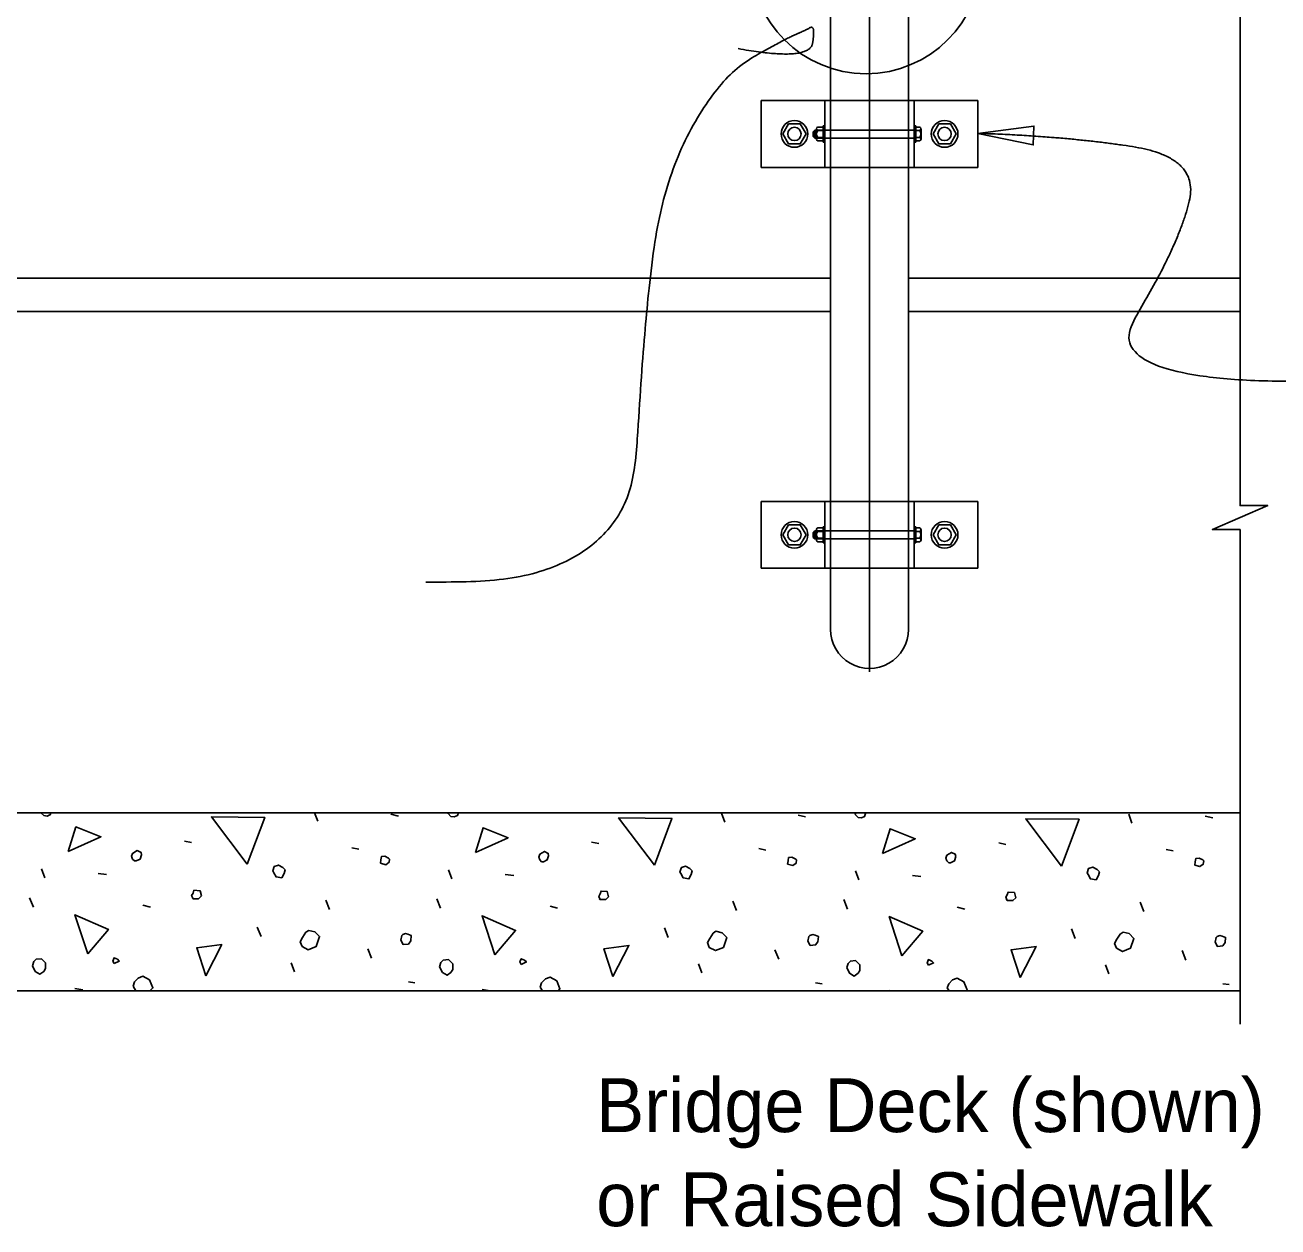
# Model space of a CAD drawing. Extents: x 0 to 41.2, y 0 to 26.
# Drawn here: x 19.046 to 23.735, y 12.586 to 17.084 of the extents above; entities that cross this region are included whole.
import ezdxf

# ---------------------------------------------------------------- set-up
doc = ezdxf.new("R2010")
doc.units = 0
for name, color, linetype in [('CL_Major', 7, 'Continuous'), ('Dimension', 7, 'Continuous'), ('Miscellaneous', 7, 'Continuous'), ('SteelMisc', 7, 'Continuous'), ('SteelMisc_h', 7, 'Continuous'), ('SupstrConc', 7, 'Continuous')]:
    doc.layers.add(name, color=color, linetype=linetype)

msp = doc.modelspace()

# ---------------------------------------------------------------- linework, layer by layer
at = {"layer": 'CL_Major'}
msp.add_line((22.2062, 25.5043), (22.2062, 14.6639), dxfattribs=at)
at = {"layer": 'Dimension'}
for points in [[(23.5932, 20.1983), (23.5932, 19.1806), (23.6966, 19.1806), (23.5932, 19.1356), (23.4899, 19.0906), (23.5932, 19.0906), (23.5932, 16.8862)], [(23.5932, 17.1362), (23.5932, 15.2854), (23.6966, 15.2854), (23.5932, 15.2404), (23.4899, 15.1954), (23.5932, 15.1954), (23.5932, 13.3448)]]:
    msp.add_lwpolyline(points, dxfattribs=at)
msp.add_lwpolyline([(22.6122, 16.6783), (22.819, 16.6352), (22.8216, 16.7057)], close=True, dxfattribs=at)
msp.add_circle((22.1934, 17.3332), 0.4318, dxfattribs=at)
for points in [[(20.5456, 14.9991), (21.3049, 14.9652), (21.3652, 16.0213), (21.4405, 16.5191), (21.6515, 16.8963), (21.8903, 17.0313), (21.9647, 17.0631), (22.0043, 17.0848), (21.982, 16.9466), (21.7151, 16.9952)], [(23.9932, 15.7529), (23.0399, 15.7236), (23.3618, 16.2556), (23.4433, 16.5898), (22.9335, 16.6682), (22.6122, 16.6783)]]:
    msp.add_open_spline(points, degree=2, dxfattribs=at)
at = {"layer": 'Miscellaneous'}
for p, q in [((21.9986, 16.6691), (21.9986, 16.6812)), ((22.0044, 16.6691), (22.0044, 16.6812)), ((21.9986, 15.1691), (21.9986, 15.1812)), ((22.0044, 15.1691), (22.0044, 15.1812)), ((20.141, 14.1043), (20.1292, 14.1361)), ((20.415, 14.1308), (20.4432, 14.1237)), ((21.6648, 14.1008), (21.6524, 14.1344)), ((21.9388, 14.1273), (21.9671, 14.1202)), ((23.1886, 14.0972), (23.1762, 14.1308)), ((23.4626, 14.1237), (23.4909, 14.1167)), ((19.6424, 14.0301), (19.669, 14.0247)), ((21.1663, 14.0265), (21.1928, 14.0212)), ((22.6901, 14.023), (22.7166, 14.0177)), ((20.2682, 14.0053), (20.2947, 14)), ((21.792, 14.0018), (21.8186, 13.9965)), ((23.3159, 13.9982), (23.3424, 13.9929)), ((19.1192, 13.8922), (19.1068, 13.9258)), ((19.3189, 13.9081), (19.3508, 13.9045)), ((20.643, 13.8886), (20.6306, 13.9222)), ((20.8428, 13.9045), (20.8746, 13.901)), ((22.1668, 13.8851), (22.1544, 13.9187)), ((22.3666, 13.901), (22.3984, 13.8975)), ((19.0768, 13.7826), (19.0626, 13.8179)), ((19.4869, 13.7896), (19.5152, 13.7826)), ((20.1851, 13.7737), (20.171, 13.8091)), ((20.6006, 13.779), (20.5864, 13.8144)), ((21.0107, 13.7861), (21.039, 13.779)), ((21.709, 13.7702), (21.6948, 13.8055)), ((22.1244, 13.7755), (22.1102, 13.8108)), ((23.2328, 13.7667), (23.2186, 13.802)), ((22.5345, 13.7826), (22.5628, 13.7755)), ((19.9288, 13.673), (19.9147, 13.7083)), ((21.4526, 13.6694), (21.4385, 13.7048)), ((22.9765, 13.6659), (22.9623, 13.7012)), ((20.3425, 13.5916), (20.3283, 13.627)), ((21.8663, 13.5881), (21.8522, 13.6235)), ((23.3901, 13.5846), (23.376, 13.6199)), ((20.0543, 13.5404), (20.042, 13.574)), ((21.5781, 13.5368), (21.5658, 13.5704)), ((23.102, 13.5333), (23.0896, 13.5669)), ((19.2323, 13.4785), (19.2624, 13.4732)), ((20.4804, 13.5033), (20.5051, 13.4997)), ((20.7561, 13.475), (20.7862, 13.4697)), ((22.0042, 13.4997), (22.0289, 13.4962)), ((22.28, 13.4714), (22.2912, 13.4695)), ((23.528, 13.4962), (23.5527, 13.4927))]:
    msp.add_line(p, q, dxfattribs=at)
for points in [[(19.105, 14.1361), (19.1156, 14.1255)], [(19.1156, 14.1255), (19.128, 14.1237), (19.1404, 14.129), (19.1428, 14.1361)], [(19.8776, 13.9434), (19.7432, 14.1202), (19.943, 14.1184), (19.8776, 13.9434)], [(20.63, 14.1361), (20.6289, 14.1326), (20.6395, 14.122)], [(20.6395, 14.122), (20.6518, 14.1202), (20.6642, 14.1255), (20.6677, 14.1361)], [(21.4014, 13.9399), (21.267, 14.1167), (21.4668, 14.1149), (21.4014, 13.9399)], [(22.155, 14.1361), (22.1527, 14.129), (22.1633, 14.1184)], [(22.1633, 14.1184), (22.1757, 14.1167), (22.188, 14.122), (22.1916, 14.1326), (22.1894, 14.1361)], [(19.2076, 13.9912), (19.2359, 14.0831), (19.3295, 14.046), (19.2076, 13.9912)], [(20.7314, 13.9876), (20.7597, 14.0796), (20.8534, 14.0424), (20.7314, 13.9876)], [(22.2552, 13.9841), (22.2835, 14.076), (22.3772, 14.0389), (22.2552, 13.9841)], [(22.9252, 13.9364), (22.7908, 14.1131), (22.9906, 14.1114), (22.9252, 13.9364)], [(19.4551, 13.9558), (19.4621, 13.9558), (19.4763, 13.9629), (19.4816, 13.9788), (19.4798, 13.9876), (19.4657, 13.9947), (19.448, 13.9841), (19.4445, 13.9735), (19.448, 13.9629), (19.4551, 13.9558)], [(20.3761, 13.947), (20.3955, 13.9417), (20.4079, 13.9505), (20.4097, 13.9629), (20.4061, 13.9664), (20.392, 13.9735), (20.3796, 13.9717), (20.3778, 13.9593), (20.3761, 13.947)], [(20.9789, 13.9523), (20.9859, 13.9523), (21.0001, 13.9593), (21.0054, 13.9753), (21.0036, 13.9841), (20.9895, 13.9912), (20.9718, 13.9806), (20.9683, 13.9699), (20.9718, 13.9593), (20.9789, 13.9523)], [(22.5027, 13.9487), (22.5098, 13.9487), (22.5239, 13.9558), (22.5292, 13.9717), (22.5274, 13.9806), (22.5133, 13.9876), (22.4956, 13.977), (22.4921, 13.9664), (22.4956, 13.9558), (22.5027, 13.9487)], [(19.9766, 13.9116), (19.9854, 13.8957), (20.0066, 13.8922), (20.0154, 13.9081), (20.019, 13.9222), (20.0101, 13.9311), (19.9942, 13.9399), (19.9783, 13.9346), (19.973, 13.9187), (19.9766, 13.9116)], [(21.5004, 13.9081), (21.5092, 13.8922), (21.5304, 13.8886), (21.5393, 13.9045), (21.5428, 13.9187), (21.534, 13.9275), (21.518, 13.9364), (21.5021, 13.9311), (21.4968, 13.9151), (21.5004, 13.9081)], [(21.8999, 13.9434), (21.9193, 13.9381), (21.9317, 13.947), (21.9335, 13.9593), (21.9299, 13.9629), (21.9158, 13.9699), (21.9034, 13.9682), (21.9016, 13.9558), (21.8999, 13.9434)], [(23.0242, 13.9045), (23.033, 13.8886), (23.0542, 13.8851), (23.0631, 13.901), (23.0666, 13.9151), (23.0578, 13.924), (23.0419, 13.9328), (23.0259, 13.9275), (23.0206, 13.9116), (23.0242, 13.9045)], [(23.4237, 13.9399), (23.4431, 13.9346), (23.4555, 13.9434), (23.4573, 13.9558), (23.4537, 13.9593), (23.4396, 13.9664), (23.4272, 13.9646), (23.4255, 13.9523), (23.4237, 13.9399)], [(19.6743, 13.8144), (19.6955, 13.8144), (19.7061, 13.825), (19.7008, 13.8444), (19.6778, 13.8462), (19.6743, 13.8356), (19.669, 13.8268), (19.6743, 13.8144), (19.6707, 13.8179)], [(21.1981, 13.8108), (21.2193, 13.8108), (21.2299, 13.8215), (21.2246, 13.8409), (21.2016, 13.8427), (21.1981, 13.8321), (21.1928, 13.8232), (21.1981, 13.8108), (21.1945, 13.8144)], [(22.7219, 13.8073), (22.7431, 13.8073), (22.7537, 13.8179), (22.7484, 13.8374), (22.7254, 13.8391), (22.7219, 13.8285), (22.7166, 13.8197), (22.7219, 13.8073), (22.7184, 13.8108)], [(19.2801, 13.6076), (19.2323, 13.7543), (19.3578, 13.6995), (19.2801, 13.6076)], [(20.8039, 13.604), (20.7561, 13.7507), (20.8816, 13.6959), (20.8039, 13.604)], [(22.3277, 13.6005), (22.28, 13.7472), (22.4055, 13.6924), (22.3277, 13.6005)], [(20.0826, 13.6358), (20.1056, 13.6235), (20.1356, 13.6358), (20.148, 13.673), (20.1303, 13.6906), (20.1074, 13.6959), (20.0968, 13.6889), (20.0844, 13.6694), (20.0755, 13.6535), (20.0826, 13.6358)], [(21.6064, 13.6323), (21.6294, 13.6199), (21.6595, 13.6323), (21.6718, 13.6694), (21.6542, 13.6871), (21.6312, 13.6924), (21.6206, 13.6853), (21.6082, 13.6659), (21.5994, 13.65), (21.6064, 13.6323)], [(20.4521, 13.6588), (20.4609, 13.6429), (20.4804, 13.6447), (20.4892, 13.6571), (20.491, 13.6765), (20.4786, 13.6818), (20.4698, 13.6836), (20.4592, 13.68), (20.4556, 13.6765), (20.4521, 13.6588)], [(21.9759, 13.6553), (21.9847, 13.6394), (22.0042, 13.6411), (22.013, 13.6535), (22.0148, 13.673), (22.0024, 13.6783), (21.9936, 13.68), (21.983, 13.6765), (21.9794, 13.673), (21.9759, 13.6553)], [(23.1302, 13.6288), (23.1532, 13.6164), (23.1833, 13.6288), (23.1957, 13.6659), (23.178, 13.6836), (23.155, 13.6889), (23.1444, 13.6818), (23.132, 13.6624), (23.1232, 13.6464), (23.1302, 13.6288)], [(23.4997, 13.6518), (23.5085, 13.6358), (23.528, 13.6376), (23.5368, 13.65), (23.5386, 13.6694), (23.5262, 13.6747), (23.5174, 13.6765), (23.5068, 13.673), (23.5032, 13.6694), (23.4997, 13.6518)], [(19.722, 13.5262), (19.6884, 13.6305), (19.7821, 13.6429), (19.722, 13.5262)], [(21.2458, 13.5227), (21.2122, 13.627), (21.3059, 13.6394), (21.2458, 13.5227)], [(22.7696, 13.5192), (22.736, 13.6235), (22.8297, 13.6358), (22.7696, 13.5192)], [(19.0732, 13.5634), (19.0838, 13.5421), (19.1015, 13.5315), (19.1156, 13.5421), (19.1227, 13.5528), (19.1227, 13.574), (19.1068, 13.5899), (19.0874, 13.5881), (19.0785, 13.5793), (19.0732, 13.5634)], [(19.379, 13.5722), (19.3985, 13.581), (19.3914, 13.5881), (19.379, 13.5934), (19.3737, 13.581), (19.379, 13.5722)], [(20.597, 13.5598), (20.6076, 13.5386), (20.6253, 13.528), (20.6395, 13.5386), (20.6465, 13.5492), (20.6465, 13.5704), (20.6306, 13.5863), (20.6112, 13.5846), (20.6023, 13.5757), (20.597, 13.5598)], [(20.9029, 13.5687), (20.9223, 13.5775), (20.9152, 13.5846), (20.9029, 13.5899), (20.8976, 13.5775), (20.9029, 13.5687)], [(22.1209, 13.5563), (22.1315, 13.5351), (22.1491, 13.5245), (22.1633, 13.5351), (22.1703, 13.5457), (22.1703, 13.5669), (22.1544, 13.5828), (22.135, 13.581), (22.1262, 13.5722), (22.1209, 13.5563)], [(22.4267, 13.5651), (22.4461, 13.574), (22.4391, 13.581), (22.4267, 13.5863), (22.4214, 13.574), (22.4267, 13.5651)], [(19.5132, 13.4695), (19.524, 13.4803), (19.5116, 13.5103), (19.4869, 13.5245), (19.4692, 13.5174), (19.4551, 13.5033), (19.4498, 13.4873)], [(21.0405, 13.4695), (21.0478, 13.4767), (21.0354, 13.5068), (21.0107, 13.5209), (20.993, 13.5139), (20.9789, 13.4997), (20.9736, 13.4838)], [(22.5679, 13.4695), (22.5716, 13.4732), (22.5593, 13.5033), (22.5345, 13.5174), (22.5168, 13.5103), (22.5027, 13.4962), (22.4974, 13.4803)], [(19.4498, 13.4873), (19.4608, 13.4695)], [(20.9736, 13.4838), (20.9825, 13.4695)], [(22.4974, 13.4803), (22.5041, 13.4695)]]:
    msp.add_lwpolyline(points, dxfattribs=at)
at = {"layer": 'SteelMisc'}
for p, q in [((22.0604, 16.801), (22.0604, 17.4631)), ((22.3521, 16.801), (22.3521, 17.4631)), ((21.8002, 16.801), (22.6122, 16.801)), ((21.8002, 16.551), (21.8002, 16.801)), ((22.0396, 16.801), (22.0396, 16.551)), ((22.3729, 16.801), (22.3729, 16.551)), ((22.6122, 16.801), (22.6122, 16.551)), ((22.008, 16.6939), (22.008, 16.6582)), ((22.0129, 16.702), (22.033, 16.702)), ((22.033, 16.7063), (22.033, 16.6457)), ((22.033, 16.7063), (22.0396, 16.7063)), ((22.033, 16.702), (22.033, 16.65)), ((22.3792, 16.7063), (22.3731, 16.7063)), ((22.3939, 16.702), (22.3791, 16.702)), ((22.3792, 16.7063), (22.3792, 16.6457)), ((22.399, 16.6566), (22.399, 16.6955)), ((21.9958, 16.684), (22.0015, 16.6906)), ((21.9958, 16.6663), (21.9958, 16.684)), ((21.9958, 16.6663), (22.0015, 16.6607)), ((22.0015, 16.6906), (22.008, 16.6906)), ((22.0015, 16.6607), (22.0015, 16.6906)), ((22.0015, 16.6607), (22.008, 16.6607)), ((22.0127, 16.689), (22.033, 16.689)), ((22.0127, 16.6631), (22.033, 16.6631)), ((22.013, 16.65), (22.033, 16.65)), ((22.394, 16.689), (22.3791, 16.689)), ((22.394, 16.663), (22.3791, 16.663)), ((22.3939, 16.65), (22.3791, 16.65)), ((22.033, 16.6457), (22.0396, 16.6457)), ((22.3792, 16.6457), (22.3731, 16.6457)), ((22.6122, 16.551), (21.8002, 16.551)), ((22.0604, 16.551), (22.0604, 15.301)), ((22.3521, 16.551), (22.3521, 15.301)), ((21.8002, 15.301), (22.6122, 15.301)), ((21.8002, 15.051), (21.8002, 15.301)), ((22.0396, 15.301), (22.0396, 15.051)), ((22.3729, 15.301), (22.3729, 15.051)), ((22.6122, 15.301), (22.6122, 15.051)), ((22.008, 15.1939), (22.008, 15.1582)), ((22.0129, 15.202), (22.033, 15.202)), ((22.033, 15.2063), (22.033, 15.1457)), ((22.033, 15.2063), (22.0396, 15.2063)), ((22.033, 15.202), (22.033, 15.15)), ((22.3792, 15.2063), (22.3731, 15.2063)), ((22.3939, 15.202), (22.3791, 15.202)), ((22.3792, 15.2063), (22.3792, 15.1457)), ((22.399, 15.1566), (22.399, 15.1955)), ((21.9958, 15.184), (22.0015, 15.1906)), ((21.9958, 15.1663), (21.9958, 15.184)), ((21.9958, 15.1663), (22.0015, 15.1607)), ((22.0015, 15.1906), (22.008, 15.1906)), ((22.0015, 15.1607), (22.0015, 15.1906)), ((22.0015, 15.1607), (22.008, 15.1607)), ((22.0127, 15.189), (22.033, 15.189)), ((22.0127, 15.1631), (22.033, 15.1631)), ((22.013, 15.15), (22.033, 15.15)), ((22.394, 15.189), (22.3791, 15.189)), ((22.394, 15.163), (22.3791, 15.163)), ((22.3939, 15.15), (22.3791, 15.15)), ((22.033, 15.1457), (22.0396, 15.1457)), ((22.3792, 15.1457), (22.3731, 15.1457)), ((22.6122, 15.051), (21.8002, 15.051)), ((22.0603, 15.051), (22.0603, 14.8218)), ((22.3519, 14.8218), (22.3519, 15.051))]:
    msp.add_line(p, q, dxfattribs=at)
for points in [[(21.9036, 16.7135), (21.9469, 16.7135), (21.9686, 16.676), (21.9469, 16.6385), (21.9036, 16.6385), (21.8819, 16.676)], [(22.4655, 16.7135), (22.5089, 16.7135), (22.5305, 16.676), (22.5089, 16.6385), (22.4655, 16.6385), (22.4439, 16.676)], [(21.9036, 15.2135), (21.9469, 15.2135), (21.9686, 15.176), (21.9469, 15.1385), (21.9036, 15.1385), (21.8819, 15.176)], [(22.4655, 15.2135), (22.5089, 15.2135), (22.5305, 15.176), (22.5089, 15.1385), (22.4655, 15.1385), (22.4439, 15.176)]]:
    msp.add_lwpolyline(points, close=True, dxfattribs=at)
for centre, radius in [((21.9252, 16.676), 0.05), ((21.9252, 16.676), 0.025), ((22.4872, 16.676), 0.05), ((22.4872, 16.676), 0.025), ((21.9252, 15.176), 0.05), ((21.9252, 15.176), 0.025), ((22.4872, 15.176), 0.05), ((22.4872, 15.176), 0.025)]:
    msp.add_circle(centre, radius, dxfattribs=at)
for centre, radius, start, end in [((22.0145, 16.6955), 0.00674, 104.4891, 254.1889), ((22.3922, 16.6955), 0.00673, 285.7823, 75.5404), ((22.0274, 16.676), 0.0196, 138.628, 221.372), ((22.0145, 16.6565), 0.00673, 105.7823, 255.5404), ((22.3922, 16.6565), 0.00674, 284.4891, 74.1889), ((22.3793, 16.676), 0.0196, 318.628, 41.372), ((22.0145, 15.1955), 0.00674, 104.4891, 254.1889), ((22.3922, 15.1955), 0.00673, 285.7823, 75.5404), ((22.0274, 15.176), 0.0196, 138.628, 221.372), ((22.0145, 15.1565), 0.00673, 105.7823, 255.5404), ((22.3922, 15.1565), 0.00674, 284.4891, 74.1889), ((22.3793, 15.176), 0.0196, 318.628, 41.372)]:
    msp.add_arc(centre, radius, start, end, dxfattribs=at)
msp.add_ellipse((22.2062, 14.8218), major_axis=(0, 0.1458), ratio=0.999499, start_param=1.570796, end_param=4.712389, dxfattribs=at)
at = {"layer": 'SteelMisc_h'}
for p, q in [((22.0604, 16.801), (22.0604, 16.551)), ((22.3521, 16.801), (22.3521, 16.551)), ((22.3729, 16.6906), (22.008, 16.6906)), ((22.008, 16.6607), (22.3729, 16.6607)), ((22.0604, 15.301), (22.0604, 15.051)), ((22.3521, 15.301), (22.3521, 15.051)), ((22.3729, 15.1906), (22.008, 15.1906)), ((22.008, 15.1607), (22.3729, 15.1607))]:
    msp.add_line(p, q, dxfattribs=at)
at = {"layer": 'SupstrConc'}
for p, q in [((12.3521, 16.1361), (22.0604, 16.1361)), ((22.3521, 16.1361), (23.5931, 16.1361)), ((12.3521, 16.0111), (22.0604, 16.0111)), ((22.3521, 16.0111), (23.5931, 16.0111)), ((0.8193, 14.1361), (23.5931, 14.1361)), ((0.8193, 13.4695), (23.5931, 13.4695))]:
    msp.add_line(p, q, dxfattribs=at)

# ---------------------------------------------------------------- texts
at = {"layer": 'Dimension'}
for s, p in [('Bridge Deck (shown)', (21.1833, 12.9409)), ('or Raised Sidewalk', (21.1833, 12.5889))]:
    msp.add_text(s, height=0.2016, dxfattribs=at).set_placement(p)

doc.saveas('drawing.dxf')
